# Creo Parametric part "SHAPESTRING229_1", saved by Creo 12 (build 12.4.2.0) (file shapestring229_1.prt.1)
Units: Custom; MM, KILOGRAM, SECS

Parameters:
  PTC_WM_ITERATION = "0"
  PTC_WM_VERSION = "-.0"
  PTC_WM_LIFECYCLE_STATE = "In Work"
  PTC_WM_LIFECYCLE = "MO_CADDocument"
  PTC_WM_CREATED_BY = "Maximilian Roepper (Z0017RMS: MO)"
  PTC_WM_CREATED_ON = "18-Sep-26 11:36:42 AM"
  PTC_WM_MODIFIED_BY = "Maximilian Roepper (Z0017RMS: MO)"
  PTC_WM_MODIFIED_ON = "18-Sep-26 11:36:46 AM"
  PDMLINKNUMBER = "PDM000071454935"
  PTC_WM_NAME = "shapestring229_1.prt"
  PTC_WM_NUMBER = "PDM000071454935"

Other parameters: WEIGHT, WEIGHT_FACTOR, WEIGHT_ADD, _MASS_TEMP, _DIFF_TEMP, MC_ERRORS, SUPPLIER

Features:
  1. coordinate system
  2. datum plane "PRT_YZ"
  3. datum plane "PRT_XY"
  4. datum plane "PRT_XZ"
  5. coordinate system
  6. datum axis
  7. datum axis
  8. datum axis
  9. coordinate system
  10. imported feature
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
Other named items: PRT, SIEMENS_MO, DRW_VIEW_ORG, PRT_X, PRT_Y, PRT_Z, CS0, ROUGH_GROB

Layers: 00_STD_CSYS-KSYS, 01_STD_PLANES-EBENEN, 02_STD_AXES-ACHSEN, 03_STD_CSYS-KSYS, 24_IMPORT_FEAT-IMPORT_KE, INTFCLR

Surfaces: 1 plane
